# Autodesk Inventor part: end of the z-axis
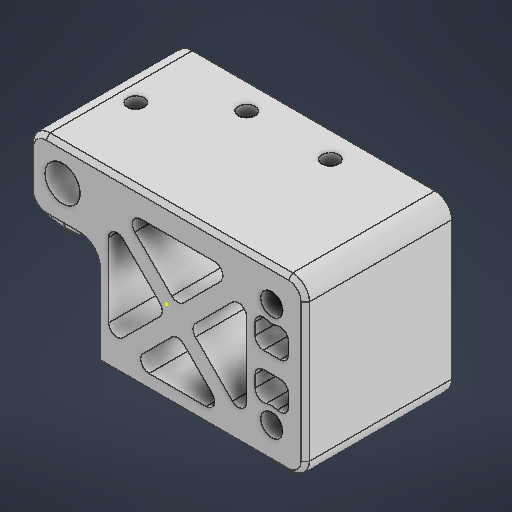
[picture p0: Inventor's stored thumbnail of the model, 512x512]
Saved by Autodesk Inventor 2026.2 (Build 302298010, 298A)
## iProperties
Created: 2026-04
Part Number: end of the z-axis
Material: 일반
Document SubType Name: Modeling
Designer: work
Density: 1 g/cm^3
Appearance: 기본값
Author: work
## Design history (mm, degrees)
sketch "스케치1"
  geometry: L1 (-25, -12.5)-(25, -12.5); L2 (25, -12.5)-(25, 12.5); L3 (25, 12.5)-(-25, 12.5); L4 (-25, 12.5)-(-25, -12.5); L5 (-25, -12.5)-(25, 12.5); L6 (25, -12.5)-(-25, 12.5); L7 (33, -20.5)-(-33, -20.5); L8 (-33, -20.5)-(-33, 20.5); L9 (-33, 20.5)-(33, 20.5); L10 (33, 20.5)-(33, -20.5); L11 (33, -20.5)-(-33, 20.5); L12 (-33, -20.5)-(33, 20.5); L13 (-33, 3.5)-(-17, 3.5); L14 (-17, 3.5)-(-17, -12.5); L15 (-17, -12.5)-(-33, -12.5); L16 (-33, -12.5)-(-33, 3.5); L17 (-17, -12.5)-(-17, -20.5); C1 r 4.2 at (-25, 12.5); C2 r 2.65 at (25, 12.5); C3 r 2.65 at (25, -12.5); 2 further points
  constraints: 34 end point, 6 parallel, 4 midpoint, 4 perpendicular, 3 centre point, 3 coincident, 3 horizontal, 3 point on line
  dimensions: "d0" = 50 distance of L2.end L3.end; "d1" = 25 distance of L3.end L1.start; "d2" = 8.4 diameter of C1; "d3" = 5.3 diameter of C2; "d4" = 5.3 diameter of C3; "d5" = 8 distance between parallel lines of L9 L3; "d6" = 8 distance between parallel lines of L10 L2; "d7" = 16 distance of L13.start L13.end; "d8" = 16 distance of L13.end L14.end
extrude "돌출1" new body sketch "스케치1" distance "d9" = 35; taper "d10" = 0 deg
sketch "스케치2"
  geometry: L1 (23, -6)-(43, -6); L2 (33, 0)-(33, -35); L3 (16, -35)-(66, -35) reference; L4 (66, 0)-(0, 0) reference; C1 r 2 at (43, -6); C2 r 2 at (23, -6); 2 further points
  constraints: 4 end point, 2 centre point, 2 coincident, 2 point on line, 1 horizontal, 1 midpoint
  dimensions: "d11" = 20 distance of L1.start L1.end; "d12" = 6 distance between parallel lines of L4 L1; "d13" = 4 diameter of C1; "d14" = 4 diameter of C2
extrude "돌출2" cut sketch "스케치2" distance "d15" = 5; taper "d16" = 0 deg
sketch "스케치3"
  geometry: 1 further point
sketch "스케치4"
  geometry: L1 (35, 37.2)-(35, 28.8) reference; L2 (0, 37.2)-(0, 28.8) reference; L3 (35, 41)-(35, 24) reference; L4 (35, 33)-(0, 33); L5 (35, 0)-(35, 41) reference; L6 (35, 20.5)-(0, 20.5); L7 (0, 41)-(0, 24) reference; L8 (0, 24)-(35, 24) reference; L9 (35, 41)-(35, 24) reference; L10 (0, 41)-(35, 41) reference; L11 (17.5, 20.5)-(17.5, 8); L12 (21.5, 3.5)-(13.5, 3.5); L13 (13.5, 3.5)-(13.5, 12.5); L14 (13.5, 12.5)-(21.5, 12.5); L15 (21.5, 12.5)-(21.5, 3.5); L16 (21.5, 3.5)-(13.5, 12.5); L17 (13.5, 3.5)-(21.5, 12.5); L18 (21.5, 12.5)-(35, 24); L19 (13.5, 12.5)-(0, 24); L20 (35, 0)-(0, 0); L21 (0, 0)-(0, 3.5); L22 (0, 3.5)-(35, 3.5); L23 (35, 3.5)-(35, 0); 1 further point
  constraints: 30 end point, 7 midpoint, 4 parallel, 3 horizontal, 2 perpendicular, 1 point on line, 1 vertical
  dimensions: "d17" = 12.5 distance from line of L6.start L4; "d18" = 12.5 distance of L11.start L11.end; "d19" = 8 distance of L13.end L14.end; "d20" = 9 distance of L12.end L13.end; "d21" = 35 distance between parallel lines of L5 L21
  node "투영된 루프1"
  node "투영된 루프2"
node "작업 평면1"
sketch "스케치5"
  geometry: L1 (35, 33.7)-(35, 24); L2 (0, 42)-(0, 24); L3 (35, 41)-(35, 24); L4 (35, 33)-(0, 33); L5 (35, 0)-(35, 41); L6 (35, 20.5)-(0, 20.5); L7 (0, 41)-(0, 24); L8 (0, 24)-(35, 24); L9 (35, 41)-(35, 24); L10 (0, 41)-(35, 41); L11 (21.5, 3.5)-(13.5, 3.5); L12 (13.5, 3.5)-(13.5, 12.5); L13 (13.5, 12.5)-(21.5, 12.5); L14 (21.5, 12.5)-(21.5, 3.5); L15 (21.5, 3.5)-(13.5, 12.5); L16 (13.5, 3.5)-(21.5, 12.5); L17 (21.5, 12.5)-(35, 24); L18 (13.5, 12.5)-(0, 24); L19 (35, 0)-(0, 0); L20 (0, 0)-(0, 3.5); L21 (0, 3.5)-(35, 3.5); L22 (35, 3.5)-(35, 0); L23 (0, 0)-(0, 41) reference; L24 (0, 41)-(35, 41) reference; L25 (35, 0)-(35, 41) reference; L26 (0, 0)-(35, 0) reference; L27 (0, 24)-(35, 24) reference; L28 (17.5, 12.5)-(17.5, 24); 6 further points
  constraints: 46 end point, 6 midpoint, 5 perpendicular, 4 coincident, 4 parallel, 3 horizontal, 2 point on line, 1 collinear
  dimensions: "d22" = 12.5 distance from line of L6.start L4; "d24" = 8 distance of L12.end L13.end; "d25" = 9 distance of L11.end L12.end; "d26" = 35 distance between parallel lines of L5 L20; "d27" = 35 distance of L2.end L8.end; "d28" = 11.5 distance of L28.start L28.end
revolve "회전1" sketch "스케치5" stored, may be unused: angle "d29" = 90 deg
sketch "스케치6"
  geometry: L1 (-8, 15.564)-(-8, -15.564) reference; A1 r 17.5 centre (0, 0) between (-8, 15.564) and (-8, -15.564) reference; 1 further point
extrude "돌출3" cut sketch "스케치6" extent not by distance; stored distance "d30" = 0; taper "d31" = 0 deg
sketch "스케치7"
  geometry: C1 r 2 at (0, 0); 1 further point
  constraints: 1 centre point
  dimensions: "d32" = 4 diameter of C1
extrude "돌출4" cut sketch "스케치7" extent not by distance; stored distance "d33" = 0; taper "d34" = 0 deg
sketch "스케치8"
  geometry: L1 (35, 24)-(35, 0) reference; L2 (35, 3.5)-(0, 3.5); L3 (0, 0)-(35, 0) reference; L4 (35, 1.75)-(0, 1.75); L5 (0, 24)-(0, 0) reference; C1 r 1.5 at (25, 1.75); C2 r 1.5 at (10, 1.75); 1 further point
  constraints: 5 point on line, 4 end point, 2 centre point, 2 horizontal
  dimensions: "d35" = 35 distance of L2.start L2.end; "d36" = 3.5 distance between parallel lines of L3 L2; "d37" = 1.75 distance between parallel lines of L3 L4; "d38" = 3 diameter of C1; "d39" = 3 diameter of C2; "d40" = 10 distance of L4.start C1.centre; "d41" = 10 distance of L4.end C2.centre
extrude "돌출5" cut sketch "스케치8" distance "d42" = 5; taper "d43" = 0 deg
sketch "스케치9"
  geometry: L1 (0, 24)-(1.936, 24) reference; L2 (0, 24)-(0, 0) reference; L3 (0, 0)-(35, 0) reference; L4 (35, 24)-(35, 0) reference; L5 (33.064, 24)-(35, 24) reference; C1 r 1.5 at (10, 1.75) reference; C2 r 1.5 at (25, 1.75) reference; C3 r 3 at (25, 1.75); C4 r 3 at (10, 1.75); 5 further points
  constraints: 2 centre point, 2 coincident, 1 horizontal alignment
  dimensions: "d44" = 6 diameter of C4; "d45" = 6 diameter of C3
extrude "돌출6" join sketch "스케치9" distance "d46" = 5; taper "d47" = 0 deg
sketch "스케치10"
  geometry: L1 (-19, 14.5)-(14, 14.5); L2 (14, 14.5)-(14, -16.5); L3 (14, -16.5)-(-19, -16.5); L4 (-19, -16.5)-(-19, 14.5); L5 (-33, 20.5)-(33, 20.5) reference; L6 (-33, -20.5)-(-33, 20.5) reference; L7 (17, -20.5)-(-33, -20.5) reference; L8 (17, 3.5)-(17, -20.5) reference; L9 (25, 3.5)-(17, 3.5) reference; L10 (33, 3.5)-(25, 3.5) reference; L11 (33, 20.5)-(33, 3.5) reference; L12 (-19, -15.672)-(11.172, 14.5); L13 (14, 11.672)-(-14.172, -16.5); L14 (-19, 11.672)-(9.172, -16.5); L15 (14, -15.672)-(-16.172, 14.5); L16 (-19, 11.672)-(-16.172, 14.5); L17 (14, 11.672)-(11.172, 14.5); L18 (-29, 12.5)-(-29, -12.5); L19 (-21, -12.5)-(-21, 12.5); L20 (-29, 2)-(-21, 2); L21 (-21, -2)-(-29, -2); L22 (-28.992, 0)-(-21, 0); C1 r 4.2 at (25, 12.5) reference; C2 r 2.65 at (-25, 12.5) reference; C3 r 2.65 at (-25, -12.5) reference; A1 r 4 centre (-25, 12.5) between (-29, 12.5) and (-21, 12.5); A2 r 4 centre (-25, -12.5) between (-29, -12.5) and (-21, -12.5); 5 further points
  constraints: 30 end point, 18 point on line, 5 parallel, 4 perpendicular, 4 point on circle, 2 centre point, 2 coincident, 2 tangent, 2 vertical, 1 horizontal, 1 midpoint
  dimensions: "d48" = 4 distance between parallel lines of L15 L14; "d49" = 4 distance between parallel lines of L13 L12; "d50" = 4 distance between parallel lines of L7 L3; "d51" = 6 distance between parallel lines of L5 L1; "d52" = 3 distance between parallel lines of L8 L2; "d53" = 6 distance from line of C3.centre L4; "d54" = 45 deg angle of L3 L14; "d55" = 45 deg angle of L3 L13; "d56" = 8 diameter of A1; "d57" = 8 diameter of A2; "d58" = 2 distance between parallel lines of L20 L22; "d59" = 4 distance between parallel lines of L21 L20
extrude "돌출7" cut sketch "스케치10" extent not by distance; stored distance "d60" = 0; taper "d61" = 0 deg
fillet "모깎기1" dims "d62" = 2
fillet "모깎기2" dims "d63" = 4
sketch "스케치11"
  geometry: L1 (4, -30.563)-(20, -30.563); L2 (20, -30.563)-(20, -22.563); L3 (20, -22.563)-(4, -22.563); L4 (4, -22.563)-(4, -30.563); L5 (4, -26.563)-(20, -26.563); L6 (12, -22.563)-(12, -26.563); C1 r 1.5 at (7.8, -26.563); C2 r 1.5 at (16.2, -26.563); 1 further point
  constraints: 12 end point, 4 midpoint, 2 centre point, 2 parallel, 1 coincident, 1 horizontal, 1 perpendicular, 1 point on line, 1 symmetric about line, 1 other
  dimensions: "d64" = 3 diameter of C1; "d67" = 8.4 distance of C2.centre C1.centre; "d68" = 16 distance of L1.start L1.end; "d69" = 8 distance of L1.end L2.end
extrude "돌출8" join sketch "스케치11" stored distance "d65" = 5; taper "d66" = 0 deg
fillet "모깎기3" dims "d70" = 4
fillet "모깎기4" dims "d71" = 1.22
chamfer "모따기1" distance "d72" = 1; stored, may be unused: second distance "d73" = 2, angle "d74" = 45 deg
node "솔리드1"
node "투영된 루프3"
node "투영된 루프4"
node "투영된 루프5"
node "투영된 루프6"
